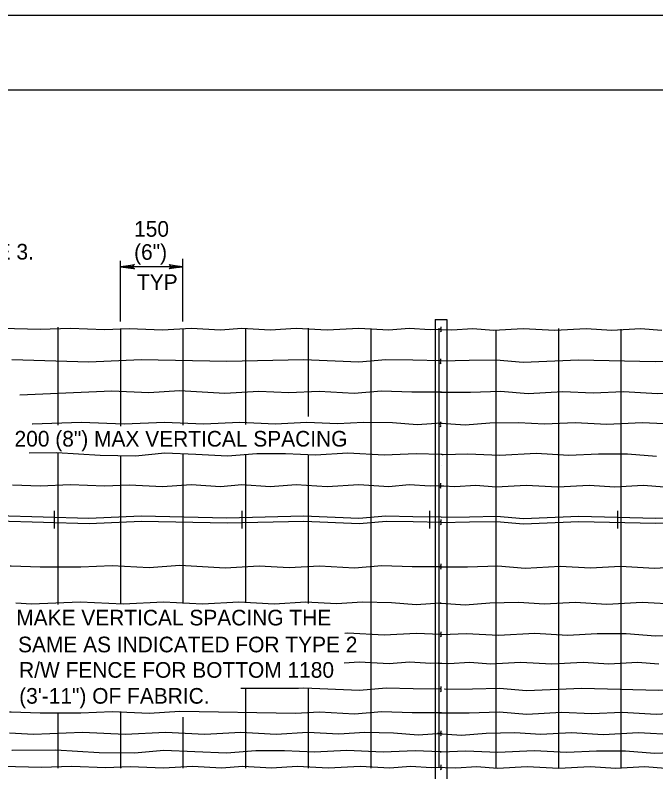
# Model space of a CAD drawing. Extents: x 13 to 918, y -903 to 879.
# Drawn here: x 317.7 to 445.7, y 727.8 to 878.9 of the extents above; entities that cross this region are included whole.
import ezdxf

# ---------------------------------------------------------------- set-up
doc = ezdxf.new("R2010")
doc.units = 0
for name, color, linetype in [('1', 7, 'Continuous'), ('2', 7, 'Continuous'), ('3', 7, 'Continuous'), ('PLT-BNDY', 7, 'Continuous')]:
    doc.layers.add(name, color=color, linetype=linetype)

msp = doc.modelspace()

# ---------------------------------------------------------------- linework, layer by layer
at = {"layer": '1'}
msp.add_lwpolyline([(839.2505, 299.93025), (839.2505, 863.93025), (53.2505, 863.93025), (53.2505, 299.93025), (839.2505, 299.93025), (839.2505, 326.28925), (639.2505, 326.28925), (639.2505, 390.96675), (839.2505, 390.96675), (839.2505, 419.93025), (639.2505, 419.93025), (639.2505, 299.93025), (718.052, 299.93025), (718.052, 326.28925), (718.052, 299.93025), (795.052, 299.93025), (795.052, 326.28925), (795.052, 313.97275), (839.2505, 313.97275)], dxfattribs=at)
at = {"layer": '2'}
for p, q in [((351.2105, 817.75375), (351.2105, 830.26)), ((338.7105, 817.75375), (338.7105, 829.837)), ((351.2105, 828.664), (338.7105, 828.664)), ((401.598, 818.15575), (403.948, 818.15575)), ((401.598, 818.15575), (401.598, 718.185)), ((403.948, 818.15575), (403.948, 718.2265)), ((326.2105, 816.6015), (326.2105, 807.12875)), ((363.7105, 816.39125), (363.7105, 797.1515)), ((376.2105, 816.39125), (376.2105, 798.77475)), ((402.30425, 816.39125), (402.30425, 728.56625)), ((338.7105, 816.29525), (338.7105, 796.84525)), ((351.2105, 816.29525), (351.2105, 796.9975)), ((388.7105, 816.29525), (388.7105, 728.47025)), ((413.7105, 816.085), (413.7105, 728.47025)), ((426.2105, 816.29525), (426.2105, 728.47025)), ((438.7105, 816.18075), (438.7105, 728.47025)), ((326.2105, 807.12875), (326.2105, 796.9975)), ((326.2105, 791.53075), (326.2105, 761.20575)), ((338.7105, 790.78275), (338.7105, 761.35775)), ((351.2105, 791.37875), (351.2105, 761.35775)), ((363.7105, 791.2245), (363.7105, 761.66625)), ((376.2105, 791.091), (376.2105, 761.35775)), ((402.773, 789.05575), (402.773, 789.05575)), ((325.49375, 779.87025), (325.49375, 776.34125)), ((362.99375, 779.87025), (362.99375, 776.34125)), ((400.49375, 779.87025), (400.49375, 776.34125)), ((437.99375, 779.87025), (437.99375, 776.34125)), ((402.773, 777.587), (402.773, 777.587)), ((402.773, 768.73275), (402.773, 768.73275)), ((402.773, 761.44125), (402.773, 761.44125)), ((402.773, 755.19125), (402.773, 755.19125)), ((402.773, 749.462), (402.773, 749.462)), ((363.7105, 744.44625), (363.7105, 728.47025)), ((376.2105, 744.364), (376.2105, 728.47025)), ((402.773, 744.25375), (402.773, 744.25375)), ((326.2105, 739.6265), (326.2105, 728.47025)), ((338.7105, 739.77875), (338.7105, 728.47025)), ((402.773, 739.56625), (402.773, 739.56625)), ((351.2105, 738.648), (351.2105, 728.47025)), ((402.773, 735.3995), (402.773, 735.3995)), ((402.773, 731.75375), (402.773, 731.75375)), ((402.773, 728.62875), (402.773, 728.62875))]:
    msp.add_line(p, q, dxfattribs=at)
for points in [[(402.773, 815.585), (402.75625, 815.7765), (402.7875, 815.887), (402.7605, 816.035), (402.79375, 816.1765), (402.75625, 816.335), (402.7835, 816.49325), (402.773, 816.68075)], [(402.70225, 816.12875), (402.773, 816.139), (400.62725, 816.04525), (396.42725, 816.314), (392.323, 815.97025), (386.35625, 816.314), (380.046, 815.97025), (373.79175, 816.314), (368.65225, 815.97025), (362.95425, 816.314), (358.696, 815.97025), (352.86475, 816.314), (347.1105, 815.97025), (340.45425, 816.25775), (335.50625, 816.04525), (328.75425, 816.314), (322.65425, 816.10375), (315.021, 816.314)], [(402.84375, 816.12875), (402.773, 816.139), (404.91875, 816.04525), (409.11875, 816.314), (413.223, 815.97025), (419.18975, 816.314), (425.5, 815.97025), (431.75425, 816.314), (436.89375, 815.97025), (442.59175, 816.314), (446.85, 815.97025)], [(402.7, 809.92025), (402.773, 809.889), (397.15625, 809.9765), (391.76675, 810.0725), (386.375, 809.612), (375.3085, 810.0725), (359.98125, 809.70775), (342.871, 810.0725), (332.37925, 809.612), (317.0125, 810.07875)], [(402.698, 809.1975), (402.68125, 809.389), (402.7125, 809.4995), (402.6855, 809.6475), (402.71875, 809.789), (402.68125, 809.9475), (402.7085, 810.10575), (402.698, 810.29325)], [(402.846, 809.92025), (402.773, 809.889), (408.38975, 809.9765), (413.77925, 810.0725), (419.171, 809.612), (430.2375, 810.0725), (445.56475, 809.70775), (462.675, 810.0725), (473.16675, 809.612), (491.46675, 810.16825), (510.24375, 809.612), (529.5605, 810.264), (547.496, 809.51625), (552.773, 809.889)], [(402.68125, 803.61825), (402.773, 803.639), (396.90625, 803.639), (390.8835, 803.81), (385.398, 803.3495), (378.41475, 803.735), (372.373, 803.44525), (366.35, 803.735), (359.5605, 803.3495), (350.54375, 803.90575), (344.40625, 803.44525), (336.9835, 803.81), (318.60925, 803.01725)], [(402.86475, 803.61825), (402.773, 803.639), (408.63975, 803.639), (414.6625, 803.81), (420.148, 803.3495), (427.13125, 803.735), (433.173, 803.44525), (439.196, 803.735), (445.9855, 803.3495), (455.00225, 803.90575), (461.13975, 803.44525), (468.5625, 803.81), (474.796, 803.54125), (482.96875, 803.54125), (488.74175, 803.735), (495.33975, 804.0015), (502.898, 803.4265), (508.748, 803.5225), (516.2875, 803.69525), (525.1105, 803.98275), (534.125, 803.4265), (540.821, 803.887), (546.47925, 803.5225), (552.773, 803.639)], [(402.548, 797.37875), (402.773, 797.389), (397.98125, 797.085), (393.05225, 797.46825), (387.296, 797.564), (382.098, 797.2765), (375.9605, 797.564), (369.63125, 797.18075), (362.571, 797.564), (355.321, 797.18075), (347.51475, 797.564), (339.4375, 797.18075), (330.8835, 797.564), (321.11875, 797.18075), (321.08125, 797.18275)], [(402.698, 796.614), (402.68125, 796.80575), (402.7125, 796.91625), (402.6855, 797.064), (402.71875, 797.20575), (402.68125, 797.364), (402.7085, 797.5225), (402.698, 797.71)], [(402.998, 797.37875), (402.773, 797.389), (407.56475, 797.085), (412.49375, 797.46825), (418.25, 797.564), (423.448, 797.2765), (429.5855, 797.564), (435.91475, 797.18075), (442.975, 797.564), (450.225, 797.18075), (458.03125, 797.564), (466.1085, 797.18075), (474.6625, 797.564), (484.42725, 797.18075), (492.3105, 797.64125), (499.90625, 797.10375), (509.01675, 797.564), (519.4335, 797.10375), (529.65625, 797.564), (538.19175, 797.00775), (547.66875, 797.564), (552.773, 797.37875)], [(402.96875, 791.12875), (402.773, 791.139), (397.82725, 791.31625), (391.421, 791.02875), (384.171, 791.39325), (377.66675, 791.02875), (371.721, 791.31625), (365.948, 791.31625), (360.098, 790.837), (353.7855, 791.1245), (347.55225, 791.39325), (341.70225, 790.837), (334.64375, 790.93275), (325.99175, 791.489), (320.47925, 791.42875)], [(402.96875, 791.12875), (403.16475, 791.139), (408.1105, 791.31625), (414.51675, 791.02875), (421.76675, 791.39325), (428.271, 791.02875), (434.21675, 791.31625), (439.98975, 791.31625), (445.83975, 790.837)], [(402.548, 784.87875), (402.773, 784.889), (400.62725, 784.79525), (396.42725, 785.064), (392.323, 784.72025), (386.35625, 785.064), (380.046, 784.72025), (373.79175, 785.064), (368.65225, 784.72025), (362.95425, 785.064), (358.696, 784.72025), (352.86475, 785.064), (347.1105, 784.72025), (340.45425, 785.00775), (335.50625, 784.79525), (328.75425, 785.064), (322.65425, 784.85375), (317.17925, 785.00375)], [(402.698, 784.337), (402.68125, 784.52875), (402.7125, 784.639), (402.6855, 784.787), (402.71875, 784.92875), (402.68125, 785.087), (402.7085, 785.24525), (402.698, 785.43275)], [(402.773, 784.889), (403.35425, 784.862), (405.5, 784.76825), (409.7, 785.037), (413.80425, 784.69325), (419.771, 785.037), (426.08125, 784.69325), (432.3355, 785.037), (437.475, 784.69325), (443.173, 785.037), (447.43125, 784.69325)], [(402.773, 778.639), (402.773, 778.639), (397.15625, 778.7265), (391.76675, 778.8225), (386.375, 778.362), (375.3085, 778.8225), (359.98125, 778.45775), (342.871, 778.8225), (332.37925, 778.362), (314.07925, 778.91825), (303.173, 778.59525)], [(402.773, 778.639), (402.81475, 778.639), (408.43125, 778.7265), (413.821, 778.8225), (419.2125, 778.362), (430.27925, 778.8225), (445.60625, 778.45775), (462.71675, 778.8225), (473.2085, 778.362), (491.5085, 778.91825), (510.2855, 778.362), (529.60225, 779.014), (547.5375, 778.26625), (552.81475, 778.639)], [(402.773, 777.587), (402.84375, 777.587), (397.22725, 777.6745), (391.8375, 777.77025), (386.446, 777.31), (375.37925, 777.77025), (360.05225, 777.40575), (342.94175, 777.77025), (332.45, 777.31), (314.15, 777.86625), (302.86675, 777.53275)], [(402.773, 777.039), (402.75625, 777.23075), (402.7875, 777.34125), (402.7605, 777.489), (402.79375, 777.63075), (402.75625, 777.789), (402.7835, 777.9475), (402.773, 778.135)], [(402.773, 777.587), (402.81475, 777.587), (408.43125, 777.6745), (413.821, 777.77025), (419.2125, 777.31), (430.27925, 777.77025), (445.60625, 777.40575), (462.71675, 777.77025), (473.2085, 777.31), (491.5085, 777.86625), (510.2855, 777.31), (529.60225, 777.962), (547.5375, 777.214), (552.81475, 777.587)], [(402.773, 768.73275), (402.773, 768.73275), (396.97725, 768.73275), (390.95425, 768.90375), (385.46875, 768.44325), (378.4855, 768.82875), (372.44375, 768.539), (366.421, 768.82875), (359.63125, 768.44325), (350.61475, 768.9995), (344.47725, 768.539), (337.05425, 768.90375), (330.821, 768.635), (322.648, 768.635), (316.875, 768.82875), (316.71675, 768.835)], [(402.26875, 768.73275), (402.26875, 768.73275), (408.06475, 768.73275), (414.0875, 768.90375), (419.573, 768.44325), (426.55625, 768.82875), (432.598, 768.539), (438.621, 768.82875), (445.4105, 768.44325), (454.42725, 768.9995), (460.56475, 768.539), (467.9875, 768.90375), (474.221, 768.635), (482.39375, 768.635), (488.16675, 768.82875), (494.76475, 769.09525), (502.323, 768.52025), (508.173, 768.61625), (515.7125, 768.789), (524.5355, 769.0765), (533.55, 768.52025), (540.246, 768.98075), (545.90425, 768.61625), (552.198, 768.73275)], [(402.773, 768.185), (402.75625, 768.3765), (402.7875, 768.487), (402.7605, 768.635), (402.79375, 768.7765), (402.75625, 768.935), (402.7835, 769.09325), (402.773, 769.28075)], [(402.773, 761.44125), (402.57725, 761.4515), (397.7855, 761.1475), (392.85625, 761.53075), (387.1, 761.6265), (381.90225, 761.339), (375.76475, 761.6265), (369.4355, 761.24325), (362.375, 761.6265), (355.125, 761.24325), (347.31875, 761.6265), (339.24175, 761.24325), (330.6875, 761.6265), (320.923, 761.24325), (317.7875, 761.4265)], [(402.57725, 761.44125), (402.773, 761.4515), (407.56475, 761.1475), (412.49375, 761.53075), (418.25, 761.6265), (423.448, 761.339), (429.5855, 761.6265), (435.91475, 761.24325), (442.975, 761.6265), (450.225, 761.24325), (458.03125, 761.6265), (466.1085, 761.24325), (474.6625, 761.6265), (484.42725, 761.24325), (492.3105, 761.70375), (499.90625, 761.16625), (509.01675, 761.6265), (519.4335, 761.16625), (529.65625, 761.6265), (538.19175, 761.07025), (547.66875, 761.6265), (552.773, 761.44125)], [(402.773, 755.19125), (402.73125, 755.2015), (397.7855, 755.37875), (391.37925, 755.09125), (384.12925, 755.45575), (383.5335, 755.4225)], [(402.773, 754.64325), (402.75625, 754.835), (402.7875, 754.94525), (402.7605, 755.09325), (402.79375, 755.235), (402.75625, 755.39325), (402.7835, 755.5515), (402.773, 755.739)], [(402.8855, 755.19125), (402.92725, 755.2015), (407.873, 755.37875), (414.27925, 755.09125), (421.52925, 755.45575), (428.0335, 755.09125), (433.97925, 755.37875), (439.75225, 755.37875), (445.60225, 754.8995), (451.91475, 755.187)], [(402.773, 749.462), (402.84375, 749.4725), (400.698, 749.37875), (396.498, 749.6475), (392.39375, 749.30375), (386.42725, 749.6475), (383.3875, 749.48275)], [(402.26875, 749.462), (402.198, 749.4725), (404.34375, 749.37875), (408.54375, 749.6475), (412.648, 749.30375), (418.61475, 749.6475), (424.925, 749.30375), (431.17925, 749.6475), (436.31875, 749.30375), (442.01675, 749.6475), (446.275, 749.30375)], [(374.27725, 744.42025), (362.769, 744.42425)], [(402.771, 744.29525), (402.84375, 744.264), (397.22725, 744.3515), (391.8375, 744.4475), (386.446, 743.987), (375.37925, 744.4475), (374.27725, 744.42025)], [(402.773, 743.70575), (402.75625, 743.8975), (402.7875, 744.00775), (402.7605, 744.15575), (402.79375, 744.2975), (402.75625, 744.45575), (402.7835, 744.614), (402.773, 744.8015)], [(403.5, 744.29525), (403.42725, 744.264), (409.04375, 744.3515), (414.4335, 744.4475), (419.825, 743.987), (430.89175, 744.4475), (446.21875, 744.08275), (463.32925, 744.4475), (473.821, 743.987), (492.121, 744.54325), (510.898, 743.987), (530.21475, 744.639), (548.15, 743.89125), (553.42725, 744.264)], [(373.69175, 739.44325), (350.61475, 739.84325), (344.47725, 739.38275), (337.05425, 739.7475), (330.821, 739.47875), (322.648, 739.47875), (316.875, 739.6725), (316.548, 739.685)], [(402.75225, 739.55575), (402.84375, 739.5765), (396.97725, 739.5765), (390.95425, 739.7475), (385.46875, 739.287), (378.4855, 739.6725), (373.69175, 739.44325)], [(402.598, 739.55575), (402.50625, 739.5765), (408.373, 739.5765), (414.396, 739.7475), (419.88125, 739.287), (426.86475, 739.6725), (432.90625, 739.38275), (438.92925, 739.6725), (445.71875, 739.287), (454.7355, 739.84325), (460.873, 739.38275), (468.296, 739.7475), (474.52925, 739.47875), (482.70225, 739.47875), (488.475, 739.6725), (495.073, 739.939), (502.63125, 739.364), (508.48125, 739.46), (516.021, 739.63275), (524.84375, 739.92025), (533.8585, 739.364), (540.55425, 739.8245), (546.2125, 739.46), (552.50625, 739.5765)], [(402.773, 735.3995), (402.998, 735.41), (398.20625, 735.10575), (393.27725, 735.489), (387.521, 735.585), (382.323, 735.2975), (376.1855, 735.585), (369.85625, 735.2015), (362.796, 735.585), (355.546, 735.2015), (347.73975, 735.585), (339.6625, 735.2015), (331.1085, 735.585), (321.34375, 735.2015), (316.53125, 735.48275)], [(402.26875, 735.3995), (402.04375, 735.41), (406.8355, 735.10575), (411.76475, 735.489), (417.521, 735.585), (422.71875, 735.2975), (428.85625, 735.585), (435.1855, 735.2015), (442.246, 735.585), (449.496, 735.2015), (457.30225, 735.585), (465.37925, 735.2015), (473.9335, 735.585), (483.698, 735.2015), (491.58125, 735.662), (499.17725, 735.1245), (508.2875, 735.585), (518.70425, 735.1245), (528.92725, 735.585), (537.4625, 735.02875), (546.93975, 735.585), (552.04375, 735.3995)], [(402.773, 734.8515), (402.75625, 735.04325), (402.7875, 735.15375), (402.7605, 735.3015), (402.79375, 735.44325), (402.75625, 735.6015), (402.7835, 735.76), (402.773, 735.9475)], [(402.773, 731.75375), (402.57725, 731.764), (397.63125, 731.94125), (391.225, 731.65375), (383.975, 732.01825), (377.471, 731.65375), (371.525, 731.94125), (365.75225, 731.94125), (359.90225, 731.462), (353.58975, 731.7495), (347.35625, 732.01825), (341.50625, 731.462), (334.448, 731.55775), (325.796, 732.114), (317.06875, 732.01825), (316.99375, 732.014)], [(402.57725, 731.75375), (402.773, 731.764), (407.71875, 731.94125), (414.125, 731.65375), (421.375, 732.01825), (427.87925, 731.65375), (433.825, 731.94125), (439.598, 731.94125), (445.448, 731.462), (451.7605, 731.7495)], [(402.773, 728.62875), (402.998, 728.639), (400.85225, 728.54525), (396.65225, 728.814), (392.548, 728.47025), (386.58125, 728.814), (380.271, 728.47025), (374.01675, 728.814), (368.87725, 728.47025), (363.17925, 728.814), (358.921, 728.47025), (353.08975, 728.814), (347.3355, 728.47025), (340.67925, 728.75775), (335.73125, 728.54525), (328.97925, 728.814), (322.87925, 728.60375), (315.246, 728.814)], [(402.773, 728.08075), (402.75625, 728.2725), (402.7875, 728.38275), (402.7605, 728.53075), (402.79375, 728.6725), (402.75625, 728.83075), (402.7835, 728.989), (402.773, 729.1765)], [(403, 728.66625), (403.58125, 728.639), (405.72725, 728.54525), (409.92725, 728.814), (414.03125, 728.47025), (419.998, 728.814), (426.3085, 728.47025), (432.5625, 728.814), (437.70225, 728.47025), (443.4, 728.814), (447.6585, 728.47025)]]:
    msp.add_lwpolyline(points, dxfattribs=at)
at = {"layer": '3'}
for points in [[(341.3585, 828.33075), (341.2605, 828.5225), (338.7105, 828.664), (341.3585, 828.33075), (341.496, 828.21625), (338.7105, 828.664), (341.2585, 828.789), (341.35225, 828.98075), (338.7105, 828.664), (341.496, 829.10575), (341.35225, 828.98075)], [(348.5625, 828.9975), (348.6605, 828.80575), (351.2105, 828.664), (348.5625, 828.9975), (348.425, 829.112), (351.2105, 828.664), (348.6625, 828.539), (348.56875, 828.3475), (351.2105, 828.664), (348.425, 828.2225), (348.56875, 828.3475)]]:
    msp.add_lwpolyline(points, dxfattribs=at)
at = {"layer": 'PLT-BNDY'}
msp.add_lwpolyline([(13.2505, 878.93025), (854.2505, 878.93025), (854.2505, 284.93025), (13.2505, 284.93025)], close=True, dxfattribs=at)

# ---------------------------------------------------------------- texts
at = {"layer": '3'}
for s, height, p in [('150', 3.124999, (341.44375, 834.66125)), ('LINE POST, SEE NOTE 3.', 3.1249995, (271.49175, 830.10575)), ('(6")', 3.124999, (341.444, 830.05075)), ('TYP', 3.124999, (342.023, 824.0245)), ('200 (8") MAX VERTICAL SPACING', 3.1249995, (317.56475, 792.739)), ('MAKE VERTICAL SPACING THE', 3.1249995, (317.89175, 757.00575)), ('SAME AS INDICATED FOR TYPE 2', 3.1249995, (318.2585, 751.635)), ('R/W FENCE FOR BOTTOM 1180', 3.1249995, (318.46875, 746.5495)), ('(3\'-11") OF FABRIC.', 3.1249995, (318.48975, 741.3725))]:
    msp.add_text(s, height=height, dxfattribs=at).set_placement(p)

doc.saveas('drawing.dxf')
